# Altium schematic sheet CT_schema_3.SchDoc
size 258 x 142 mm
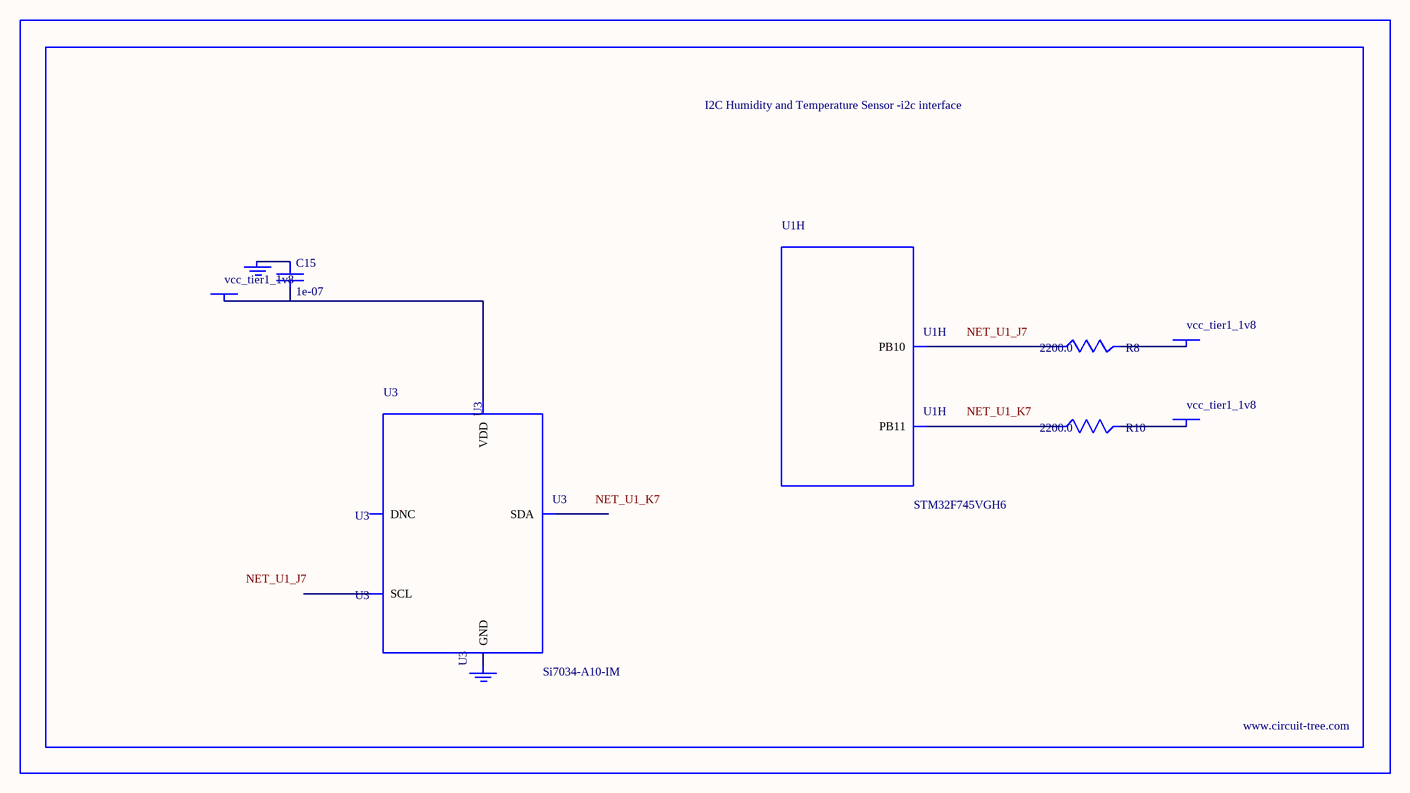
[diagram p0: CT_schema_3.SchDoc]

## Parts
BORDER2  (no value)
C15  1e-07  [C0402]
GND_INSTANCE_2_0  (no value)
GND_INSTANCE_2_1  (no value)
POWER_INSTANCE_2_0  vcc_tier1_1v8
POWER_INSTANCE_2_1  vcc_tier1_1v8
POWER_INSTANCE_2_2  vcc_tier1_1v8
R8  2200.0  [R0603]
R10  2200.0  [R0603]
U1  STM32F745VGH6  [TFBGA100]  (part H of 9)
U3  Si7034-A10-IM  [SI7034-A10-IM]

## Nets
NetC15_1: C15.1 GND_INSTANCE_2_0.0(GND)
NetC15_2: C15.2 POWER_INSTANCE_2_0.0(PWR) U3.1(VDD)
NetGND_INSTANCE_2_1_0: GND_INSTANCE_2_1.0(GND) U3.5(GND)
NetPOWER_INSTANCE_2_1_0: POWER_INSTANCE_2_1.0(PWR) R8.2
NetPOWER_INSTANCE_2_2_0: POWER_INSTANCE_2_2.0(PWR) R10.2
NetR8_1: R8.1 U1.J7(PB10)
NetR10_1: R10.1 U1.K7(PB11)

Not connected (* = marked no-connect by the designer): U3 2(SCL) 3(DNC) 4(SDA)

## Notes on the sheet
- Labels drawn without touching a wire or pin: NET_U1_J7, NET_U1_K7

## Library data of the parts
BORDER2 = BORDER_PAGE2
C15 = C0402C104K3RACTU
GND_INSTANCE_2_0 GND_INSTANCE_2_1 = GND
POWER_INSTANCE_2_0-POWER_INSTANCE_2_2 = PWR
R8 R10 = RC0603JR-072K2L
